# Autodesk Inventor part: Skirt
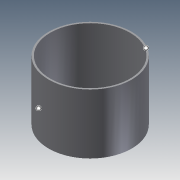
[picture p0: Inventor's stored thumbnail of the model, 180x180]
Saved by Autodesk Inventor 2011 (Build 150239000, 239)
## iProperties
Created: 2010-06
Part Number: Skirt
Document SubType Name: Modeling
Designer: mklassen
Density: 1 g/cm^3
OD: 24.000 in
THK: 0.500 in
LEN: 1.500 ft
SKVOFS: 6.000 in
Author: mklassen
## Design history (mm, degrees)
sketch "skSkirt"
  geometry: C1 r 317.5 at (0, 0); C2 r 304.8 at (0, 0); 1 further point
  constraints: 2 centre point, 1 coincident
  dimensions: "d0" = 609.6 diameter of C2 (derived); "d1" = 12.7 radial gap between concentric circles of C1 C2 (derived)
extrude "Extrusion1" new body sketch "skSkirt" stored distance "d2" = 457.2 (derived); taper "d3" = 0 deg
body "Solid1"
other parameters: "d4" = 152.4 (derived), "d5" = 0
